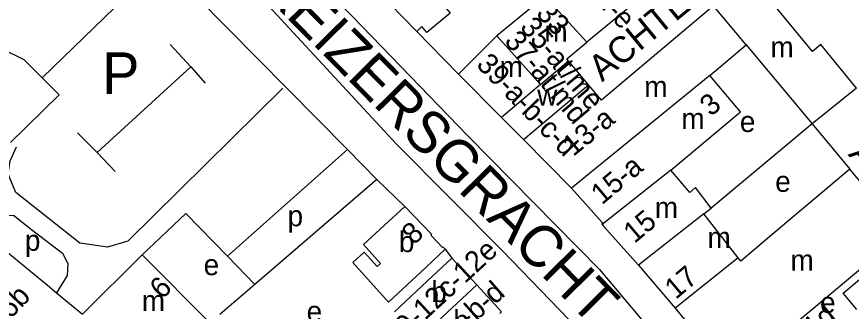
# Model space of a CAD drawing. Extents: x 160673 to 161924, y 382258 to 384145.
# Drawn here: x 161158.4 to 161318.4, y 383112.8 to 383169.3 of the extents above; entities that cross this region are included whole.
import ezdxf

# ---------------------------------------------------------------- set-up
doc = ezdxf.new("R2010")
doc.units = 0
for name, color, linetype in [('BLT_Basislijn', 7, 'Continuous'), ('BLT_Bebouwing', 7, 'Continuous'), ('BLT_Centroide', 7, 'Continuous'), ('BLT_Huisnummer', 7, 'Continuous'), ('BLT_Huisnummer_ tussenligend', 7, 'Continuous'), ('BLT_Huisnummer_reeks', 7, 'Continuous'), ('BLT_Onderdoorgang_en_onderverdeling', 7, 'Continuous'), ('BLT_Onderverdeling_panden', 7, 'Continuous'), ('BLT_Straatnaam', 7, 'Continuous'), ('BLT_Straatnaam_hoofdweg', 7, 'Continuous'), ('BLT_Tekst_parkeren', 7, 'Continuous')]:
    doc.layers.add(name, color=color, linetype=linetype)

msp = doc.modelspace()

# ---------------------------------------------------------------- linework, layer by layer
at = {"layer": 'BLT_Basislijn'}
for p, q in [((161174.28, 383192.04), (161221.81, 383143.81)), ((161163.29, 383157.58), (161180.3, 383174.05)), ((161235.13, 383166.43), (161243.15, 383158.28)), ((161187.84, 383163.94), (161191.78, 383159.69)), ((161159.81, 383161.05), (161163.29, 383157.58)), ((161173.84, 383143.25), (161191.78, 383159.69)), ((161191.78, 383159.69), (161194.57, 383156.51)), ((161163.29, 383157.58), (161166.57, 383154.31)), ((161157.21, 383145.16), (161166.57, 383154.31)), ((161310.9, 383148.73), (161291.59, 383132.55)), ((161170.09, 383147.01), (161173.84, 383143.25)), ((161221.81, 383143.81), (161198.84, 383123.32)), ((161221.81, 383143.81), (161227.46, 383138.08)), ((161173.84, 383143.25), (161177.31, 383139.59)), ((161227.46, 383138.08), (161222.83, 383134.09)), ((161227.46, 383138.08), (161232.81, 383132.87)), ((161222.83, 383134.09), (161204.09, 383117.92)), ((161182.46, 383123.62), (161190.85, 383131.54)), ((161190.85, 383131.54), (161198.84, 383123.32)), ((161240.57, 383124.66), (161241.87, 383122.97)), ((161198.84, 383123.32), (161204.09, 383117.92)), ((161204.09, 383117.92), (161197.35, 383112.16))]:
    msp.add_line(p, q, dxfattribs=at)
for points in [[(161105.33, 383250.78), (161111.05, 383249.36), (161132.16, 383235.51), (161150.93, 383223.25), (161167.67, 383211.41), (161190.11, 383189.36), (161231.21, 383144.85)], [(161151.06, 383240.13), (161165.98, 383226.24), (161194.65, 383197.92), (161222.81, 383169.35), (161244.86, 383146.49), (161270.16, 383120.77), (161279.96, 383109.14)], [(161151.4, 383165.2), (161159.81, 383161.05)], [(161209.41, 383155.55), (161179.71, 383126.22), (161175.81, 383125.09), (161170.52, 383125.84), (161158.26, 383135.53), (161156.75, 383139.06), (161157.19, 383141.64), (161158.39, 383144.3)], [(161231.21, 383144.85), (161251.57, 383124.39), (161269.86, 383105.47)], [(161155.52, 383131.12), (161157.8, 383131.22), (161161.28, 383128.45)], [(161161.28, 383128.45), (161167.18, 383123.95), (161168.22, 383121.97), (161168.08, 383119.64), (161166.06, 383116.33)], [(161155.64, 383124.92), (161164.31, 383117.78), (161166.06, 383116.33)], [(161166.06, 383116.33), (161171.02, 383112.24)]]:
    msp.add_lwpolyline(points, dxfattribs=at)
at = {"layer": 'BLT_Bebouwing'}
for p, q in [((161280.74, 383175.17), (161267.75, 383164.4)), ((161298.29, 383163.9), (161292.01, 383171.36)), ((161291.31, 383158.02), (161298.29, 383163.9)), ((161298.29, 383163.9), (161310.9, 383148.73)), ((161268.04, 383156.22), (161264.24, 383160.8)), ((161243.15, 383158.28), (161251.36, 383149.98)), ((161319.4, 383155.58), (161310.9, 383148.73)), ((161251.36, 383149.98), (161255.59, 383145.76)), ((161310.9, 383148.73), (161318.15, 383140.01)), ((161296.75, 383123.04), (161290.17, 383131.44)), ((161271.01, 383129.04), (161277.62, 383121.61)), ((161306.6, 383109.51), (161328.15, 383127.65)), ((161171.02, 383112.24), (161182.46, 383123.62)), ((161182.46, 383123.62), (161195.6, 383110.42)), ((161241.87, 383122.97), (161246.62, 383117.82)), ((161297.24, 383122.41), (161296.75, 383123.04)), ((161277.62, 383121.61), (161284.68, 383113.39))]:
    msp.add_line(p, q, dxfattribs=at)
for points in [[(161227.18, 383174.61), (161228.4, 383177.07), (161233.17, 383175.57), (161235.31, 383174.59), (161239.24, 383171.76), (161239.73, 383172.17), (161241.54, 383169.94), (161237.08, 383166.29)], [(161235.13, 383166.43), (161227.18, 383174.61)], [(161260.26, 383172.66), (161258.38, 383171.11), (161257.91, 383171.68), (161253.59, 383168.16), (161250.48, 383165.6)], [(161292.01, 383171.36), (161270.52, 383153.27), (161268.37, 383155.82), (161268.04, 383156.22)], [(161237.08, 383166.29), (161236.12, 383167.4), (161235.13, 383166.43)], [(161250.48, 383165.6), (161243.15, 383158.28)], [(161264.24, 383160.8), (161263.9, 383161.21), (161267.75, 383164.4)], [(161283.86, 383139.85), (161297.17, 383151.06), (161291.31, 383158.02)], [(161264.8, 383136.4), (161255.59, 383145.76)], [(161291.59, 383132.55), (161288.54, 383136.5), (161287.45, 383135.58), (161283.86, 383139.85)], [(161318.15, 383140.01), (161303.66, 383127.81)], [(161328.15, 383127.65), (161321.75, 383135.74), (161318.15, 383140.01)], [(161264.8, 383136.4), (161270.69, 383129.82), (161270.59, 383129.53), (161270.69, 383129.42)], [(161232.81, 383132.87), (161224.9, 383125.57), (161228.18, 383121.93), (161227.54, 383121.35), (161225.05, 383124.1), (161222.84, 383122.1), (161229.68, 383114.51), (161236.92, 383121.25), (161240.57, 383124.66)], [(161240.57, 383124.66), (161240.16, 383125.1), (161240.03, 383124.99), (161237.95, 383127.22), (161237.96, 383127.54), (161232.81, 383132.87)], [(161290.17, 383131.44), (161291.59, 383132.55)], [(161270.69, 383129.42), (161271.01, 383129.04)], [(161303.66, 383127.81), (161297.24, 383122.41)], [(161319.49, 383113.12), (161316.87, 383116.23), (161329.12, 383126.53)], [(161241.87, 383122.97), (161238.21, 383119.57), (161230.82, 383112.67)], [(161246.62, 383117.82), (161251.37, 383112.67), (161251.04, 383112.37)], [(161284.68, 383113.39), (161287.11, 383110.41), (161288.33, 383109.03), (161292.98, 383103.32), (161294.74, 383101.19)]]:
    msp.add_lwpolyline(points, dxfattribs=at)
at = {"layer": 'BLT_Onderdoorgang_en_onderverdeling'}
for points in [[(161319.4, 383155.58), (161312.56, 383163.95), (161310.96, 383162.64), (161299.07, 383177.19)], [(161258.84, 383156.27), (161251.36, 383149.98), (161251.36, 383149.98)]]:
    msp.add_lwpolyline(points, dxfattribs=at)
at = {"layer": 'BLT_Onderverdeling_panden'}
for p, q in [((161267.75, 383164.4), (161260.26, 383172.66)), ((161258.84, 383156.27), (161250.48, 383165.6)), ((161258.84, 383156.27), (161264.24, 383160.8)), ((161291.31, 383158.02), (161264.8, 383136.4)), ((161283.86, 383139.85), (161270.69, 383129.42)), ((161290.17, 383131.44), (161277.62, 383121.61)), ((161296.75, 383123.04), (161284.68, 383113.39)), ((161246.62, 383117.82), (161235.45, 383107.44))]:
    msp.add_line(p, q, dxfattribs=at)
msp.add_lwpolyline([(161255.59, 383145.76), (161268.04, 383156.22)], dxfattribs=at)

# ---------------------------------------------------------------- texts
at = {"layer": 'BLT_Centroide'}
for s, p in [('m', (161259.6, 383164.47)), ('m', (161302.93, 383161.47)), ('m', (161251, 383157.69)), ('m', (161278.73, 383153.88)), ('w', (161258.21, 383152.23)), ('m', (161285.85, 383147.74)), ('e', (161297.06, 383147.17)), ('e', (161303.84, 383135.68)), ('m', (161280.76, 383130.69)), ('p', (161210.35, 383129.08)), ('b', (161231.7, 383124.12)), ('m', (161290.86, 383124.94)), ('p', (161159.99, 383124.37)), ('m', (161306.77, 383120.59)), ('e', (161194.26, 383119.69)), ('b', (161237.91, 383114.53)), ('m', (161182.41, 383112.81)), ('e', (161312.45, 383112.46)), ('e', (161214, 383110.74)), ('b', (161242.15, 383109))]:
    msp.add_text(s, height=4, dxfattribs=at).set_placement(p)
at = {"layer": 'BLT_Huisnummer'}
for s, rotation, p in [('15', 40.0856, (161276.84, 383125.66)), ('8', 42.9815, (161234.54, 383125.35)), ('6', 44.857, (161186.32, 383114.92))]:
    msp.add_text(s, height=4, rotation=rotation, dxfattribs=at).set_placement(p)
at = {"layer": 'BLT_Huisnummer_ tussenligend'}
msp.add_text('17', height=4, rotation=40.0856, dxfattribs=at).set_placement((161284.77, 383114.92))
at = {"layer": 'BLT_Huisnummer_reeks'}
for s, rotation, p in [('31d-e', 312.2454, (161265.23, 383176.74)), ('33', 312.2454, (161257.81, 383169.77)), ('35-at/me', 310.0347, (161254.73, 383167.18)), ('37-at/md', 310.0347, (161251.74, 383164.52)), ('39-a-b-c-d', 314.0347, (161246.34, 383159.94)), ('3', 40.0876, (161291.5, 383150.02)), ('13-a', 39.2055, (161265.11, 383142.36)), ('15-a', 40.0876, (161270.62, 383133.08)), ('10-12c-12e', 42.6727, (161231.01, 383105.69)), ('12-a-b-d', 41.3852, (161237.13, 383102.55)), ('2t/m6b', 46.7678, (161150.09, 383103.54)), ('21t/m21d', 38.5751, (161298.39, 383097.4))]:
    msp.add_text(s, height=4, rotation=rotation, dxfattribs=at).set_placement(p)
at = {"layer": 'BLT_Straatnaam'}
for rotation, p in [(39.3719, (161270.64, 383156.67)), (309.3719, (161317.7, 383142.8))]:
    msp.add_text('ACHTEROM', height=5, rotation=rotation, dxfattribs=at).set_placement(p)
at = {"layer": 'BLT_Straatnaam_hoofdweg'}
msp.add_text('KEIZERSGRACHT', height=8, rotation=314.6195, dxfattribs=at).set_placement((161204.86, 383174.43))
at = {"layer": 'BLT_Tekst_parkeren'}
msp.add_text('P', height=8, dxfattribs=at).set_placement((161174.81, 383154.45))

doc.saveas('drawing.dxf')
